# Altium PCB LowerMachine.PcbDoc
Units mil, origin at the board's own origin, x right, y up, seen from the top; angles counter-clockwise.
Board outline 1968.5 x 1968.5 mil, 2 copper layers (Top Layer, Bottom Layer); 43 components, 58 nets, 171 pads, 77 vias.
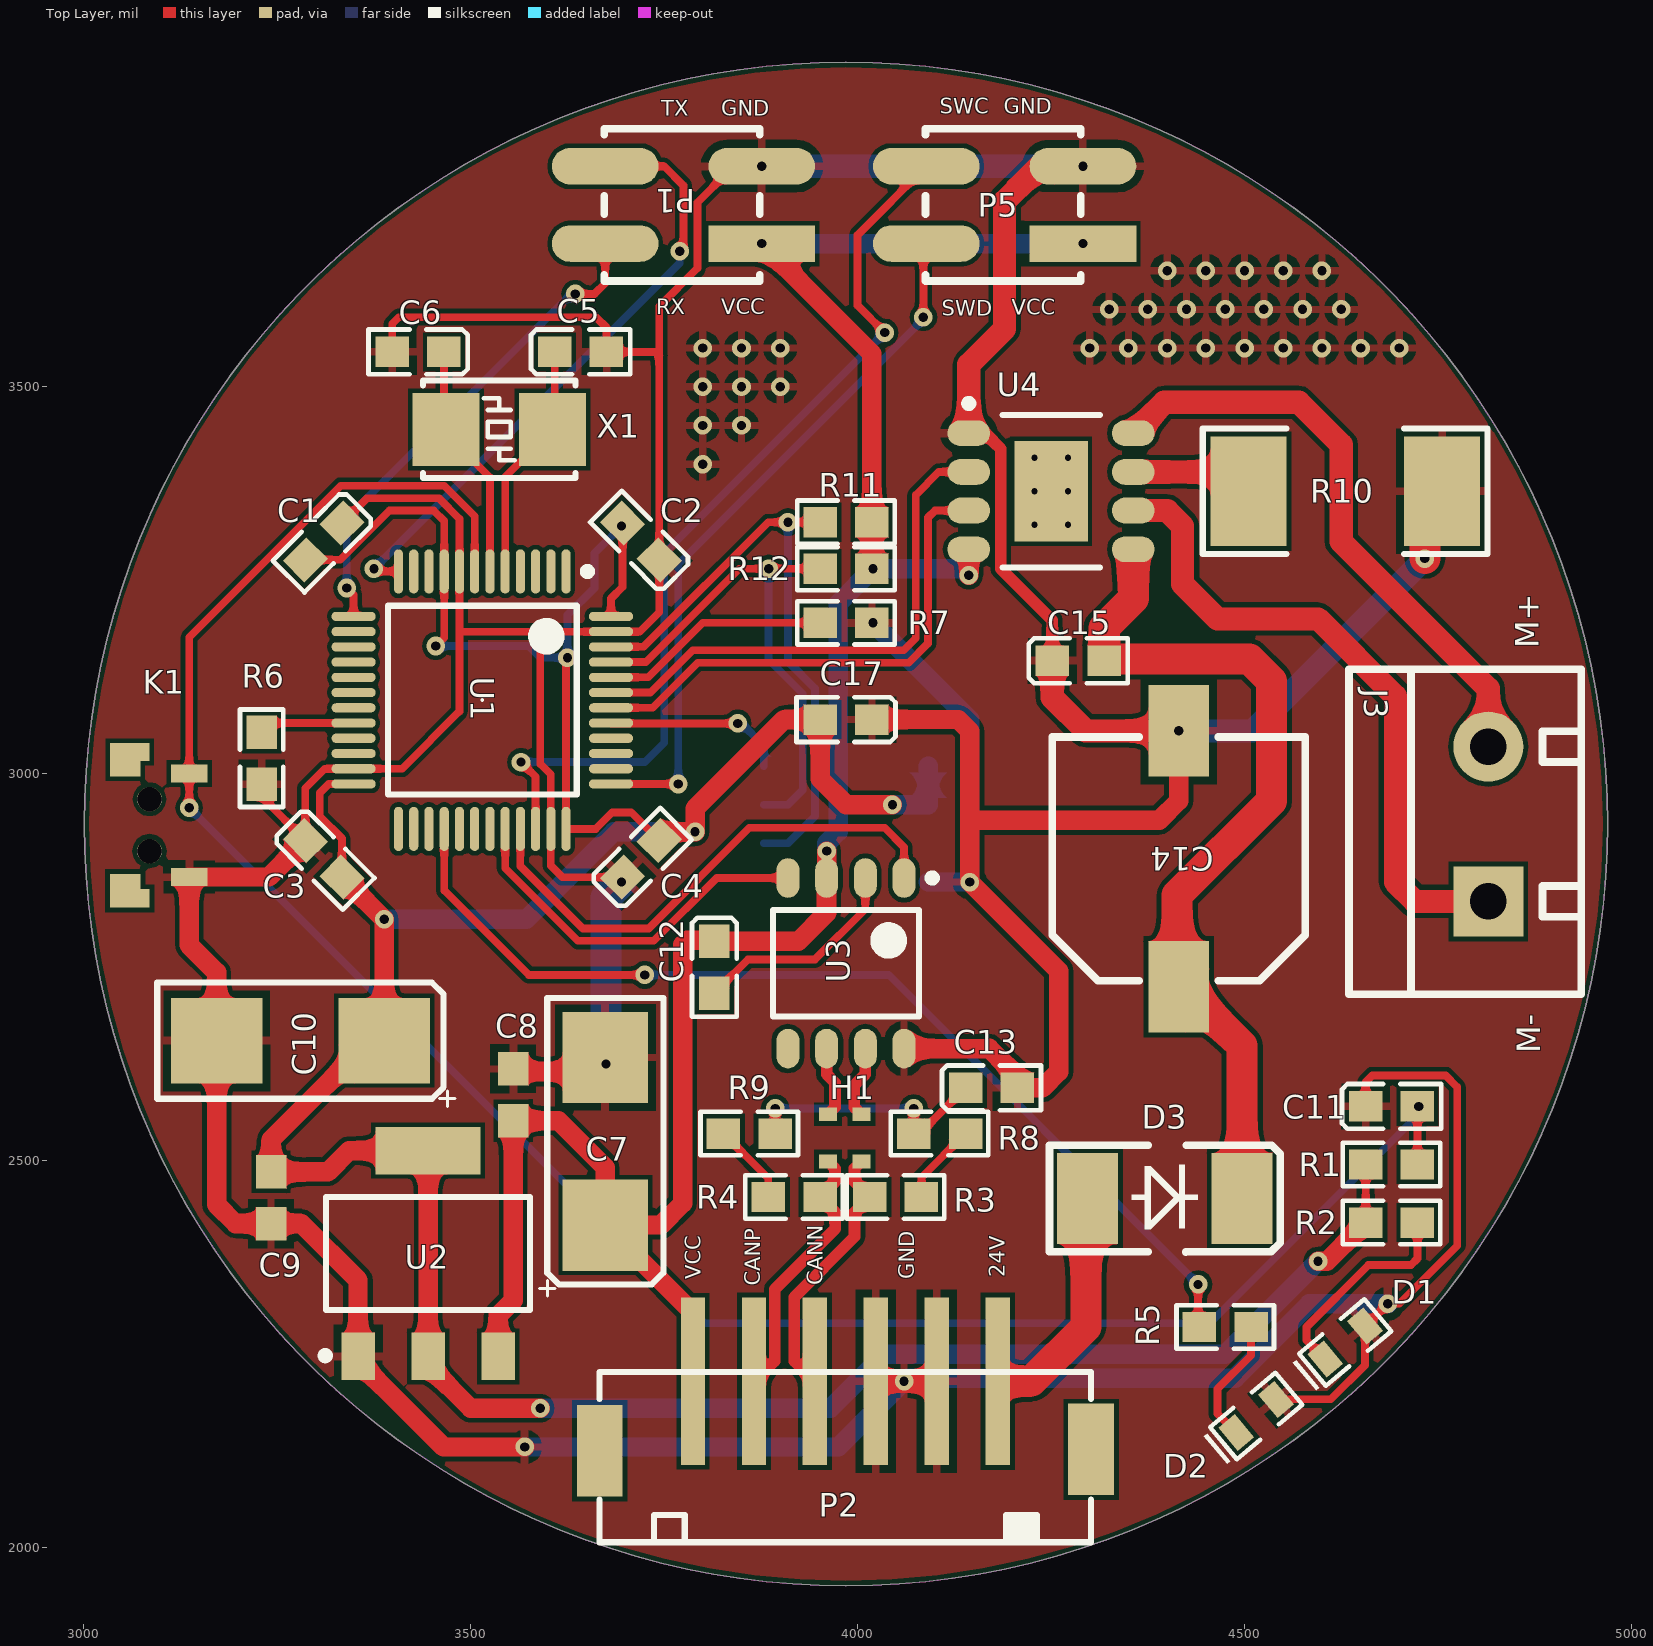
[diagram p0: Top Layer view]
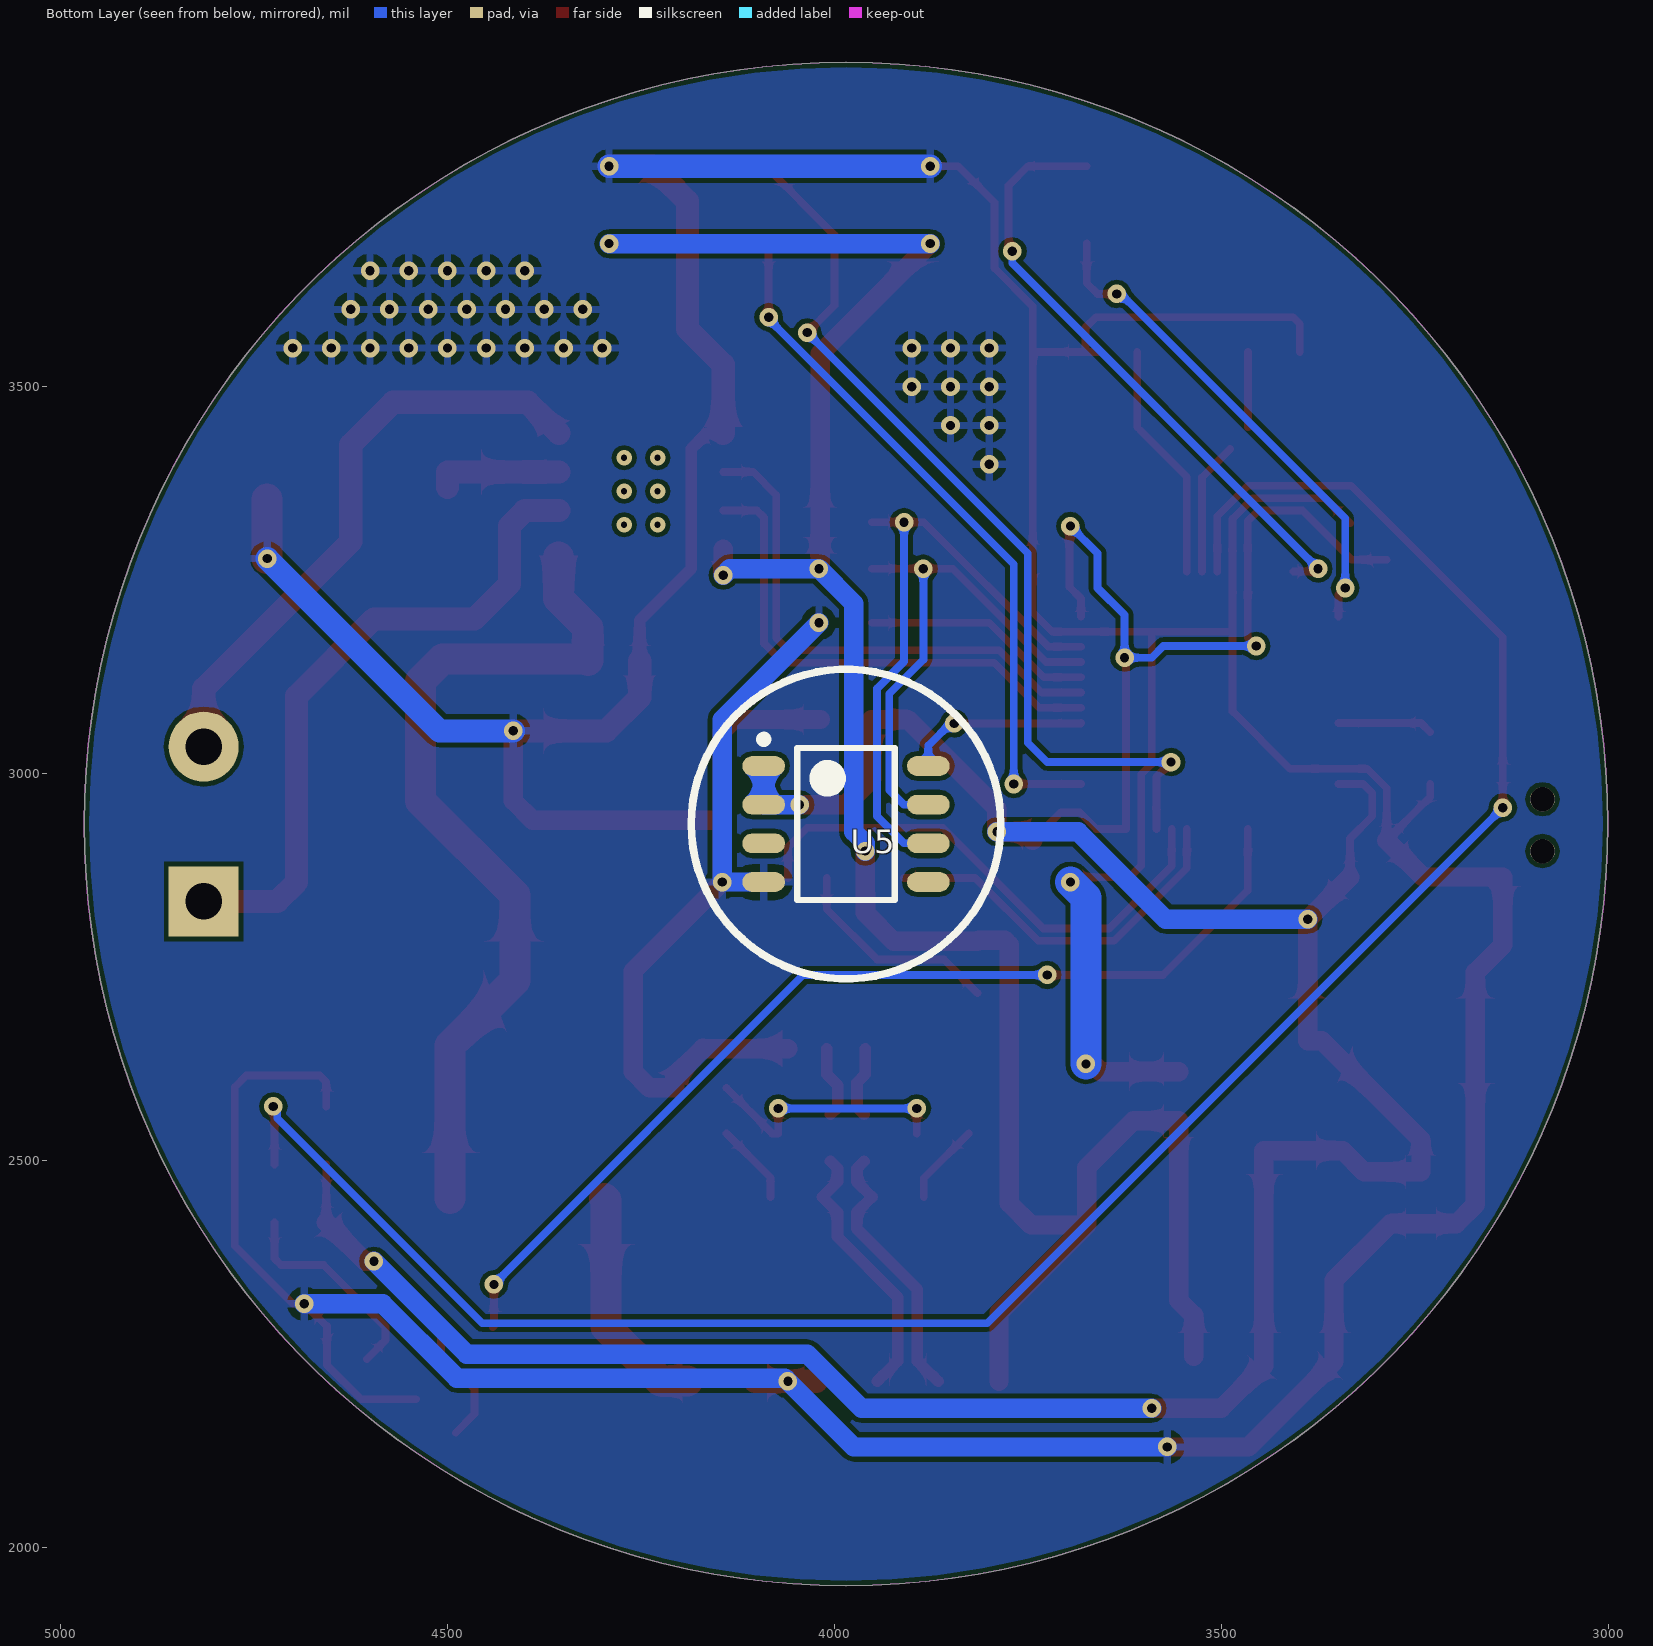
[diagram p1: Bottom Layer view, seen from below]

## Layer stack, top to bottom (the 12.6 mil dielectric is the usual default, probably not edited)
Top Solder: solder mask 0.4, Solder Resist, Dk 3.5
Top Layer: signal copper 1.4
Dielectric 1: dielectric 12.6, FR-4, Dk 4.8
Bottom Layer: signal copper 1.4
Bottom Solder: solder mask 0.4, Solder Resist, Dk 3.5

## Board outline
3000.75,2935 ccw(c3985,2935) 3985,1950.75 ccw(c3985,2935) 4969.25,2935 ccw(c3985,2935) 3985,3919.25 ccw(c3985,2935)

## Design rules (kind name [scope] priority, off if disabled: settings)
Clearance [All] p1: gap=6
DiffPairsRouting [All] p1: maxlimit=10 minlimit=10 mostfreqgap=10 toplayer_minwidth=15 toplayer_maxwidth=15 toplayer_prefwidth=15 bottomlayer_minwidth=15 bottomlayer_maxwidth=15 bottomlayer_prefwidth=15 maxuncoupledlength=500
PolygonConnect [All] p1: connectstyle=Relief reliefconductorwidth=10 reliefentries=4 polygonreliefangle="90 Angle" airgapwidth=10
RoutingVias [All] p1: holewidth=28 width=50 viastyle="Through Hole" minholewidth=28 minwidth=50 maxholewidth=28 maxwidth=50
SolderMaskExpansion [All] p1: expansion=4
Width [All] p1: maxlimit=40 minlimit=6 preferedwidth=10
29 further rules are at their usual default settings.

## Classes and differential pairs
differential pair IN: +IN_P -IN_N
differential pair CAN: +CAN_P -CAN_N

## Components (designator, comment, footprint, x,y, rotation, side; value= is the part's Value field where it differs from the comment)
C1 "104" Cap-0603 3310,3300 r225 top
C2 "104" Cap-0603 3720,3300 r135 top
C3 "104" Cap-0603 3310,2890 r315 top
C4 "104" Cap-0603 3720,2890 r45 top
C5 "22pf" Cap-0603 3642,3545 r0 top
C6 "22pf" Cap-0603 3432,3545 r180 top
C7 "100uf" tan_cap_C 3674,2525 r90 top
C8 "104" Cap-0603-M 3555,2585 r270 top
C9 "104" Cap-0603-M 3242,2452 r90 top
C10 "100uf" tan_cap_C 3280,2655 r180 top
C11 "105" Cap-0603 4690,2570 r0 top
C12 "104" Cap-0603 3815,2750 r270 top
C13 "100nf" Cap-0603 4173,2594 r0 top
C14 "100uf" CAPE_F_8X8.3X10.2 4415,2890 r270 top
C15 "220nf" Cap-0603 4285,3146 r0 top
C17 "100nf" Cap-0603 3985,3070 r180 top
D1 "LED_SMD_BLUE" LED_0603_B 4630,2265 r40 top
D2 "LED_SMD_WHITE" LED_0603_W 4515,2170 r40 top
D3 "1N5824" DO-214AC/SMA 4302,2451 r0 top
H1 "共模扼流圈" 共模扼流圈 4005,2560 r270 top
J3 "Motor interface" KF301-5.0-2P 4815,2835 r90 top
K1 "KEY" SW-SMD-2X4 3085,2900 r90 top
P1 "Header_2X2" Header_SMD_2.54X2 3775,3735 r90 top
P2 "PH2.0-6P" PH2.0S-6P 4181,2215 r180 top
P5 "Header_2X2" Header_SMD_2.54X2 4190,3735 r90 top
R1 "10K" Res-0603 4690,2495 r0 top
R2 "470R" Res-0603 4690,2420 r0 top
R3 "60R" Res-0603 4049,2453 r0 top
R4 "60R" Res-0603 3918,2453 r0 top
R5 "470" Res-0603 4475,2285 r0 top
R6 "10K" Res-0603 3230,3020 r270 top
R7 "10K" Res-0603 3985,3195 r180 top
R8 "0R" Res-0603 4106,2535 r180 top
R9 "0R" Res-0603 3860,2535 r180 top
R10 "R250" Res-2512 4630,3365 r0 top
R11 "4.7K" Res-0603 3985,3325 r180 top
R12 "4.7K" Res-0603 3985,3265 r180 top
U1 "stm32f103c8t6" stm32f103c8t6 3515,3095 r270 top
U2 "AMS1117" AMS1117 3445,2380 r0 top
U3 "tja1050" tja1050 3985,2755 r270 top
U4 "A4950" A4950 4250,3365 r0 top
U5 "AS5600" AS5600 3985,2935 r180 bottom
X1 "XTAL-2P" "OSC 5032-2P" 3537,3445 r0 top

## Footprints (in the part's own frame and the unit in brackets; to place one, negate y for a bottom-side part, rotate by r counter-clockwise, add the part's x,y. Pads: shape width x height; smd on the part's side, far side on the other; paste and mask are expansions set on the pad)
A4950 [mm] "SOIC, 8-Leads, Body 4.90x3.90mm, Pitch 1.27mm, Thermal Pad 3.30x2.41mm, IPC Medium Density"
  oval 1.4x0.85 smd: 1(-2.7,1.905) 2(-2.7,0.635) 3(-2.7,-0.635) 4(-2.7,-1.905) 5(2.7,-1.905) 6(2.7,-0.635) 7(2.7,0.635) 8(2.7,1.905)
  rect 2.41x3.3 smd: 9(0,0)
  silkscreen extent -2.82,-2.5 1.6,3, body extent -2,-2.5 2,2.5, height 1.7
AMS1117 [mm]
  rect 1.1x1.55 smd: 1(-2.3,-3.375) 2(0,-3.375) 3(2.3,-3.375)
  rect 3.45x1.55 smd: 4(0,3.375)
  silkscreen extent -3.5,-3.48 3.35,1.85, body extent -3.25,-3.48 3.25,3.48, height 1.7
AS5600 [mm] "SOIC, 8-Leads, Body 4.90x3.90mm, Pitch 1.27mm, Thermal Pad 0.00x0.00mm, IPC Medium Density"
  oval 1.4x0.65 smd: 1(-2.7,1.905) 2(-2.7,0.635) 3(-2.7,-0.635) 4(-2.7,-1.905) 5(2.7,-1.905) 6(2.7,-0.635) 7(2.7,0.635) 8(2.7,1.905)
  silkscreen extent -2.83,-2.5 1.6,2.9, body extent -2,-2.5 2,2.5, height 1.75
Cap-0603 [mm]
  rect 1.1x1 smd: 1(-0.85,0) 2(0.85,0)
  silkscreen extent -1.63,-0.74 1.63,0.74, body extent -0.8,-0.4 0.8,0.4, height 0.6
Cap-0603-M [mm]
  rect 1.1x1 smd: 1(-0.85,0) 2(0.85,0)
  body extent -0.8,-0.4 0.8,0.4, height 0.6
CAPE_F_8X8.3X10.2 [mm]
  rect 3x2 smd: 1(4.2,0) 2(-4.2,0)
  silkscreen extent -4,-4.15 4,4.15, body extent -4.95,-4.15 4.95,4.15, height 10.2
DO-214AC/SMA [mm] "塑封二极管"
  rect 2x3 smd: A(-0.127,0) K(4.953,0)
  silkscreen extent -1.37,-1.75 6.2,1.75, body extent 0.11,-1.35 4.71,1.35, height 2.4
Header_SMD_2.54X2 [mm]
  rect 1.2x3.5 smd: 1(-1.27,-2.57)
  oval 1.2x3.5 smd: 2(1.27,-2.57) 3(1.27,2.57) 4(-1.27,2.57)
  silkscreen extent -2.5,-2.5 2.5,2.6, body extent -2.58,-3.75 2.5,3.75, height 9.7
KF301-5.0-2P [mm] "可拼接端子/6A"
  rect 2.3x2.3 hole 1.2: 1(0,0)
  round 2.3 hole 1.2: 2(5.08,0)
  silkscreen extent -3.05,-3.05 7.62,4.57, body extent -3,-3.09 7.5,4.51, height 10.05
LED_0603_B [mm]
  rect 0.7x1 smd: 1(-0.85,0) 2(0.85,0)
  silkscreen extent -1.75,-0.69 1.4,0.69, body extent -0.8,-0.42 0.8,0.38, height 0.61
LED_0603_W [mm]
  rect 0.7x1 smd: 1(-0.85,0) 2(0.85,0)
  silkscreen extent -1.75,-0.69 1.4,0.69, body extent -0.8,-0.42 0.8,0.38, height 0.61
"OSC 5032-2P" [mm]
  rect 2.2x2.4 smd: 1(-1.75,0) 2(1.75,0)
  silkscreen extent -2.5,-1.6 2.5,1.6, body extent -2.5,-1.52 2.5,1.68, height 0.86
PH2.0S-6P [mm]
  rect 1.5x3 smd: 0(-3.064,2.238) 0(13.064,2.286)
  rect 0.8x5.5 smd: 1(0,0) 2(2,0) 3(4,0) 4(6,0) 5(8,0) 6(10,0)
  silkscreen extent -3.06,-0.3 13.06,5.29, body extent -3,-2.5 13,5.3, height 6.15
Res-0603 [mm]
  rect 1.1x1 smd: 1(-0.85,0) 2(0.85,0)
  silkscreen extent -1.6,-0.71 1.6,0.71, body extent -0.8,-0.4 0.8,0.4, height 0.38
Res-2512 [mm]
  rect 2.5x3.6 smd: 1(-3.175,0) 2(3.175,0)
  silkscreen extent -4.67,-2.06 4.67,2.06, body extent -3.2,-1.6 3.2,1.6, height 0.7
stm32f103c8t6 [mm] "QFP, 100-Leads, Body 14.00x20.00mm, Pitch 0.65mm, IPC Medium Density"
  oval 1.45x0.3 smd: 1(-4.225,2.75) 2(-4.225,2.25) 3(-4.225,1.75) 4(-4.225,1.25) 5(-4.225,0.75) 6(-4.225,0.25) 7(-4.225,-0.25) 8(-4.225,-0.75) 9(-4.225,-1.25) 10(-4.225,-1.75) 11(-4.225,-2.25) 12(-4.225,-2.75) 25(4.225,-2.75) 26(4.225,-2.25) 27(4.225,-1.75) 28(4.225,-1.25) 29(4.225,-0.75) 30(4.225,-0.25) 31(4.225,0.25) 32(4.225,0.75) 33(4.225,1.25) 34(4.225,1.75) 35(4.225,2.25) 36(4.225,2.75)
  oval 0.3x1.45 smd: 13(-2.75,-4.225) 14(-2.25,-4.225) 15(-1.75,-4.225) 16(-1.25,-4.225) 17(-0.75,-4.225) 18(-0.25,-4.225) 19(0.25,-4.225) 20(0.75,-4.225) 21(1.25,-4.225) 22(1.75,-4.225) 23(2.25,-4.225) 24(2.75,-4.225) 37(2.75,4.225) 38(2.25,4.225) 39(1.75,4.225) 40(1.25,4.225) 41(0.75,4.225) 42(0.25,4.225) 43(-0.25,4.225) 44(-0.75,4.225) 45(-1.25,4.225) 46(-1.75,4.225) 47(-2.25,4.225) 48(-2.75,4.225)
  silkscreen extent -4.35,-3.1 3.1,3.58, body extent -3.5,-3.5 3.5,3.5, height 1.6
SW-SMD-2X4 [mm]
  rect 0.6x1.3 smd: 0(-1.55,0.65) 0(3.25,0.65)
  rect 0.6x1 smd: 0(-1.05,0.8) 0(2.75,0.8)
  round 0.8 hole 0.8: 0(0,0) 0(1.7,0)
  rect 0.6x1.2 smd: 1(-0.85,-1.3) 3(2.55,-1.3)
  body extent -2.97,-1.8 4.83,1.8, height 3.5
tan_cap_C [mm]
  rect 3x2.8 smd: 1(-2.75,0) 2(2.75,0)
  silkscreen extent -5.08,-1.91 4.7,2.16, body extent -3.15,-1.6 3.15,1.6, height 2.5
tja1050 [mm] "SOP, 8-Leads, Body 4.90x3.90mm, Pitch 1.27mm, IPC Medium Density"
  oval 1.3x0.75 smd: 1(-2.8,1.905) 2(-2.8,0.635) 3(-2.8,-0.635) 4(-2.8,-1.905) 5(2.8,-1.905) 6(2.8,-0.635) 7(2.8,0.635) 8(2.8,1.905)
  silkscreen extent -2.92,-2.4 1.75,2.96, body extent -1.9,-2.4 1.9,2.4, height 1.75
共模扼流圈 [mm]
  rect 0.45x0.6 smd: 1(0,0) 2(0,-1.1) 3(1.55,-1.1) 4(1.55,0)

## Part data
C1 C2 C3 C4 C5 C6 C8 C9 C11 C12 C13: library part CAP
C7 C10: library part tan_cap
C14: library part CAPE-SMD, "贴片电解电容"
C15 C17: library part CAP, "贴片陶瓷电容"
D1 D2: "发光二极管"
D3: library part DIODE, "普通二极管"
J3: library part KF301-2P
R1 R2 R3 R4 R5 R6 R7 R8 R9 R10 R11 R12: library part RES, "贴片电阻"
X1: "2脚无源脚晶振"

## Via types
v1: diameter 24, hole 12, Top Layer to Bottom Layer, 71 vias
v2: diameter 19.68, hole 7.87, Top Layer to Bottom Layer, 6 vias

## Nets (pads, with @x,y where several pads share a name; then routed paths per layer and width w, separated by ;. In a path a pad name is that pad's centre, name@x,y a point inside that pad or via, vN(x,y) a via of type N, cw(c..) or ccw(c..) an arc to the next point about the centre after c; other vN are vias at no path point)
3.3V: C1.2 C2.2 C3.2 C4.2 C9.2 C10.1 C17.2 R1.1 R2.1 U1.9 U1.24 U1.36 U1.48 U2.2 U2.4 U5.1 U5.2 | length 4809.4
  Top Layer w10: C1.2 3331.34,3276.34 3395,3340 3452.37,3340 3465.79,3326.59 U1.9 3465.79,3175.79 v1(3455,3165) ; C3.2 3333.66,2916.34 3305,2945 3305,2975 3316.73,2986.73 U1.24 ; v1(3625,3150) 3623.27,3148.27 U1.36 3661.66,2928.66 3683,2950 3707.33,2950 C4.2 ; U1.48 3681.34,3226.34 3696.34,3241.34 C2.2 ; R2.1 R1.1
  Top Layer w25: C3.2 v1(3388.27,2811.73) C10.1 3370,2655 3242,2527 C9.2 3315.46,2485.46 3342.87,2512.87 U2.4 U2.2 3445,2235 3500,2180 v1(3590,2180) ; C4.2 3755,2925 v1(3790,2925) 3790,2955 3905,3070 C17.2 3951.54,2993.46 3985,2960 v1(4045,2960) ; v1(4595,2370) 4606.54,2370 R2.1
  Bottom Layer w10: v1(3455,3165) 3575,3165 3590,3150 v1(3625,3150) 3625,3205 3660,3240 3660,3285 v1(3695,3320)
  Bottom Layer w25: v1(3388.27,2811.73) 3571.73,2811.73 3685,2925 v1(3790,2925) ; v1(3590,2180) 3965,2180 4035,2250 4475,2250 v1(4595,2370) ; v1(4045,2960) U5.2 U5.1
24V: C14.1 C15.2 D3.K U4.5 | length 1132.3
  Top Layer w40: C15.2 C15.2@4318.46,3148.41 ; U4.5@4356.3,3280 4356.3,3226.3 4318.46,3188.46 C15.2@4318.46,3148.41 ; D3.K 4497,2648.65 4413,2732.65 4413,2843 4535,2965 4535,3120 4506.59,3148.41 C15.2@4318.46,3148.41
BOOT0: R7.2 U1.44 | length 299.4
  Top Layer w10: U1.44 3729.27,3124.53 3799.75,3195 R7.2
BOOT1: R6.1 U1.20 | length 123.6
  Top Layer w10: R6.1 3242.01,3065.47 U1.20
CAN_N: H1.4 P2.4 R3.1 | length 347.7
  Top Layer w15: P2.4 3937.28,2222.5 3936.5,2222.5 3918,2241 3918,2323.64 3996,2401.64 3996,2433.46 R3.1 3996,2472.54 3996,2489.98 H1.4
CAN_P: H1.3 P2.5 R4.2 | length 348.1
  Top Layer w15: P2.5 3873.54,2222.5 3874.5,2222.5 3893,2241 3893,2334 3971,2412 3971,2433.46 R4.2 3971,2472.54 3971,2489.67 H1.3
CAN_RX: U1.32 U3.4 | length 488.8
  Top Layer w10: U1.32 3544.53,2877.85 3638.37,2784 3736.63,2784 3817.86,2865.24 U3.4
CAN_TX: U1.33 U3.1 | length 681.1
  Top Layer w10: U1.33 3564.21,2880.79 3645,2800 3730,2800 3860,2930 4035,2930 4060,2905 U3.1
GND: C1.1 C2.1 C3.1 C4.1 C5.2 C6.2 C7.2 C8.1 C9.1 C10.2 C11.1 C13.2 C14.2 C15.1 C17.1 D1.2 D2.2 K1.1 P1.2 P2.2 P2.3 P5.2 R6.2 R7.1 R10.2 U1.8 U1.23 U1.35 U1.47 U2.1 U3.8 U4.1 U5.4 | length 9736.8
  Top Layer w10: R6.2 3230,2970 C3.1 3286.34,2981.34 3311.42,3006.42 U1.23 3411.42,3006.42 3485.47,3080.47 U1.8 3485.47,3329.53 3459,3356 3366,3356 C1.1 ; C6.2 3398.54,3581.54 3407,3590 3662,3590 3675.46,3576.54 C5.2 ; 3486.89,3183.58 U1.47 3718.58,3183.58 3743.66,3208.66 C2.1 3743.66,3540 ; 3590,3183.58 3590,3012.63 3603.58,2999.04 U1.35 3603.58,2881.42 3618.66,2866.34 C4.1 ; C5.2@3658.46,3545 3738.66,3545 3743.66,3540 ; v1(3876.18,3785) 3840,3785 3793,3738 3793,3653 3743.66,3603.66 3743.66,3540 ; D2.2 4611.52,2191.52 4655.64,2235.64 D1.2 4656.52,2286.52 v1(4685,2315) 4700,2315 4775,2390 4775,2595 4760,2610 4665,2610 4656.54,2601.54 C11.1
  Top Layer w15: U4.1 4165,3440 4185,3420 4185,3265 4251.54,3198.46 C15.1
  Top Layer w25: C3.1 3239.21,2866.54 K1.1 3136.18,2778.82 3171.73,2743.27 C10.2 3171.73,2443.27 3196.46,2418.54 C9.1 3281.46,2418.54 3354.45,2345.55 U2.1 3354.45,2240.55 3465,2130 v1(3570,2130) ; C8.1@3555,2615 3655.73,2615 C7.2 ; C17.1 4130,3070 4145,3055 v1(4145,2860) 4260,2745 4260,2615 4239,2594 C13.2 4206.46,2608.54 4170,2645 4169.76,2644.76 U3.8 ; 4145,2940 4390,2940 4415,2965 v1(4415,3055.35)
  Top Layer w30: P2.3 v1(4060,2215) P2.2 ; U4.1 4143.7,3528.7 4190,3575 4190,3740 4235,3785 v1(4291.18,3785) ; C15.1 4251.54,3098.46 4294.65,3055.35 v1(4415,3055.35)
  Top Layer w40: v1(4733,3278) R10.2@4733,3355
  Bottom Layer w25: v1(3570,2130) 3975,2130 v1(4060,2215) 4064,2219 4487.84,2219 4583.84,2315 v1(4685,2315) ; v1(4020,3195) 4145,3070 v1(4145,2860) U5.4
  Bottom Layer w30: v1(3876.18,3785) v1(4291.18,3785) ; v1(4415,3055.35) 4510.35,3055.35 v1(4733,3278)
  Bottom Layer w40: v1(3675,2625) 3675,2840 v1(3695,2860)
  other v1: 3800,3400 3800,3450 3850,3450 3800,3500 3850,3500 3900,3500 3800,3550 3850,3550 3900,3550 4300,3550 4350,3550 4400,3550 4450,3550 4500,3550 4550,3550 4600,3550 4650,3550 4700,3550 4325,3600 4375,3600 4425,3600 4475,3600 4525,3600 4575,3600 4625,3600 4400,3650 4450,3650 4500,3650 4550,3650 4600,3650
IN_N: H1.1 U3.7 | length 94.4
  Top Layer w15: H1.1 3995.85,2569.15 3995.85,2597.52 4010,2611.67 U3.7
IN_P: H1.2 U3.6 | length 93
  Top Layer w15: U3.6 3960,2611.67 3970.85,2600.83 3970.85,2569.15 H1.2
JTCK: P5.4 U1.37 | length 918
  Top Layer w10: U1.37 v1(3768.27,2986.73) ; v1(4085,3590) 4085,3681.18 P5.4
  Bottom Layer w10: v1(3768.27,2986.73) 3768.27,3270.74 4085,3587.47 v1(4085,3590)
JTMS: P5.3 U1.34 | length 1203.9
  Top Layer w10: v1(3565,3015) 3583.9,2996.1 U1.34 ; v1(4035,3570) 4000,3605 4000,3696.18 P5.3
  Bottom Layer w10: v1(3565,3015) 3725,3015 3750,3040 3750,3285 v1(4035,3570)
M+: J3.2 U4.8 | length 776.8
  Top Layer w30: U4.8 4396.3,3480 4570,3480 4625,3425 4625,3300 4815,3110 J3.2
M-: J3.1 U4.6 | length 852.4
  Top Layer w30: U4.6 4400,3340 4420,3320 4420,3245 4465,3200 4595,3200 4695,3100 4695,2860 4720,2835 J3.1
NetC12_2: C12.2 U3.2 | length 280.2
  Top Layer w10: C12.2 3858.46,2760 3945,2760 4010,2825 U3.2
NetC13_1: C13.1 R8.2 R9.1 | length 335.3
  Top Layer w10: R9.1 v1(3893.46,2567.46) ; R8.2@4072.46,2535.07 v1(4072.46,2567.46) ; R8.2 4080.54,2535 C13.1
  Bottom Layer w10: v1(3893.46,2567.46) v1(4072.46,2567.46)
NetD1_1: D1.1 R2.2 | length 278.2
  Top Layer w10: D1.1 4580,2267.86 4580,2285 4660,2365 4715,2365 4723.46,2373.46 R2.2
NetD2_1: D2.1 R5.2 | length 164.6
  Top Layer w10: D2.1 4465,2172.86 4465,2205 4508.46,2248.46 R5.2
NetD3_A: D3.A P2.1 | length 300.8
  Top Layer w40: P2.1@4190,2215 4225,2215 4295,2285 4295,2449 D3.A
NetR3_2: R3.2 R8.1 | length 105.6
  Top Layer w10: R3.2 4082.46,2478 R8.1
NetR4_1: R4.1 R9.2 | length 106
  Top Layer w10: R9.2 3884.54,2477 R4.1
NetR10_1: R10.1 U4.7 | length 163.7
  Top Layer w30: U4.7 4500,3390 R10.1@4500,3370
NRST: C11.2 K1.3 R1.2 U1.7 | length 2819.2
  Top Layer w10: v1(3136.18,2956.18) K1.3 3136.18,3176.18 3332,3372 3465.63,3372 3505.16,3332.47 U1.7 ; R1.2 C11.2
  Bottom Layer w10: v1(3136.18,2956.18) 3802.36,2290 4455,2290 4720,2555 4720,2565 v1(4725,2570)
OSC8M_IN: C5.1 U1.5 X1.2 | length 303.8
  Top Layer w10: U1.5 3544.53,3383.63 X1.2@3604,3443.1 ; X1.2@3608.54,3447.64 C5.1
OSC8M_OUT: C6.1 U1.6 X1.1 | length 270.6
  Top Layer w10: X1.1@3465.46,3447.64 C6.1 ; X1.1@3488.46,3419.54 3524.84,3383.16 U1.6
OSC32_IN: U1.3
OSC32_OUT: U1.4
PA0: U1.10
PA1: U1.11
PA2: P1.3 U1.12 | length 805.5
  Top Layer w10: v1(3375,3265) 3378.66,3261.34 U1.12 ; P1.3 3750,3785 3775,3760 3775,3680 v1(3770,3675)
  Bottom Layer w10: v1(3375,3265) 3770,3660 v1(3770,3675)
PA3: P1.4 U1.13 | length 641.2
  Top Layer w10: v1(3340,3240) 3348.66,3231.34 U1.13 ; v1(3635,3620) 3660,3620 3673.82,3633.82 P1.4
  Bottom Layer w10: v1(3340,3240) 3340,3330 3630,3620 v1(3635,3620)
PA4: U1.14
PA5: U1.15
PA6: U1.16
PA7: U1.17
PA8: U1.29
PA9: U1.30
PA10: U1.31
PA15: U1.38
PB0: U1.18
PB1: U1.19
PB3: U1.39
PB4: U1.40
PB5: U1.41 U5.8 | length 236.1
  Top Layer w10: U1.41 3681.81,3065 v1(3845,3065)
  Bottom Layer w10: v1(3845,3065) 3849.05,3065 3849.53,3065.47 3878.7,3036.3 U5.8
PB6: U1.42 U4.3 | length 663.2
  Top Layer w10: U1.42 3735.16,3085.16 3793.5,3143.5 4066.13,3143.5 4091,3168.37 4091,3331 4100,3340 U4.3
PB7: U1.43 U4.2 | length 688.8
  Top Layer w10: U1.43 3732.22,3104.84 3786.87,3159.5 4059.5,3159.5 4075,3175 4075,3360 4105,3390 U4.2
PB8: R12.2 U1.45 U5.7 | length 682.6
  Top Layer w10: U1.45 3726.33,3144.21 3847.12,3265 v1(3885,3265) R12.2
  Bottom Layer w10: U5.7 3910,2960 3929,2979 3929,3103.37 3885,3147.37 v1(3885,3265)
PB9: R11.2 U1.46 U5.6 | length 812.2
  Top Layer w10: U1.46 3723.39,3163.9 3884.49,3325 v1(3910,3325) R11.2
  Bottom Layer w10: U5.6 3910,2910 3945,2945 3945,3110 3910,3145 v1(3910,3325)
PB10: U1.21
PB11: U1.22
PB12: U1.25
PB13: U1.26
PB14: U1.27
PB15: R5.1 U1.28 | length 1320.2
  Top Layer w10: U1.28 3465.79,2849.21 3575,2740 v1(3725,2740) ; v1(4440,2340) 4440,2286.54 R5.1
  Bottom Layer w10: v1(3725,2740) 4040,2740 v1(4440,2340)
PC13: U1.2
VBAT: U1.1
VCC: C7.1 C8.2 C12.1 P1.1 P2.6 P5.1 R11.1 R12.1 U2.3 U3.3 U4.4 | length 2954.2
  Top Layer w25: U2.3 3535.55,2300 3555,2319.45 C8.2 3613.46,2551.54 3674,2491 C7.1 ; P2.6 3787.3,2303.43 C7.1 ; v1(3876.18,3685) 4018.46,3542.72 R11.1 R12.1 ; v1(3960,2900) U3.3 3960,2820 3923.5,2783.5 C12.1 C12.1 3813.46,2785 3780,2785 3774,2779 3774,2445 3745.73,2416.73 C7.1 ; v1(4143.7,3256.3) U4.4
  Bottom Layer w25: v1(3876.18,3685) v1(4291.18,3685) ; v1(3960,2900) 3960,2910 3975,2925 3975,3220 v1(4020,3265) 4135,3265 v1(4143.7,3256.3)
pads on no net: K1.0 P2.0 U3.5 U4.9 U5.3 U5.5
copper on no net:
  other v2: 4228.35,3321.69 4271.65,3321.69 4228.35,3365 4271.65,3365 4228.35,3408.31 4271.65,3408.31

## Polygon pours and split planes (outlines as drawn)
GND on Bottom Layer "Bottom Layer-No Net" (solid, remove dead copper, pour order 18): 2930,3940 2930,1950 2960,1920 2970,1930 5250,1930 5250,3890 5295,3935
GND on Top Layer "Bottom Layer-No Net" (solid, remove dead copper, pour order 16): 2950,3925 2960,3915 2960,1920 5110,1920 5200,2010 5040,2170 5040,3940

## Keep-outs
Keep-Out Layer:
  circle w0.5: c3985,2935 r984.25

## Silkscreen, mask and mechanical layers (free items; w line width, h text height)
Top Overlay:
  lines w5: 3392.95,3217.05 3392.95,3217.05 ; 3515,3095 3515,3095 ; 3637.05,2972.95 3637.05,2972.95
  text "SWC" at 4106,3853 h20
  text "GND" at 4189,3853 h20
  text "TX" at 3746,3850 h20
  text "GND" at 3824,3850 h20
  text "RX" at 3740,3594 h20
  text "VCC" at 3824,3594 h20
  text "VCC" at 4199,3593 h20
  text "SWD" at 4109,3592 h20
  text "M+" at 4880,3162 h30 r90
  text "M-" at 4882,2639 h30 r90
  text "24V" at 4190,2349 h20 r90
  text "VCC" at 3797,2347 h20 r90
  text "GND" at 4073,2347 h20 r90
  text "CANN" at 3955,2339 h20 r90
  text "CANP" at 3874,2338 h20 r90
Bottom Overlay:
  circle w10: c3985,2935 r200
